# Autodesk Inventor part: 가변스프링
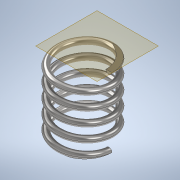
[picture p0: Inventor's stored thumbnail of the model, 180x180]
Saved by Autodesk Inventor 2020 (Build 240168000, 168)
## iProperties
Created: 2022-09
Part Number: 가변스프링
Material: 스테인레스 스틸
Document SubType Name: Modeling
Designer: 101-13
Mass: 6.62074 g
Surface Area: 16.7829 cm^2
Volume: 0.827592 cm^3
Density: 8 g/cm^3
Appearance: 반연마
Author: 101-13
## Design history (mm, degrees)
node "작업 평면1"
sketch "스케치1"
  geometry: L1 (-1.9, 22.5)-(11.4, 22.5) reference; L2 (0, 0)-(8.5, 0); L3 (8.5, 0)-(8.5, 21.871); L4 (8.5, 21.871)-(0, 21.871); L5 (0, 21.871)-(0, 0); C1 r 1 at (8.5, 0)
  constraints: 8 end point, 2 parallel, 1 centre point, 1 coincident, 1 horizontal, 1 perpendicular
  dimensions: "d1" = 22.5 distance from line of L1 L2.start (derived); "d2" = 2 diameter of C1; "d3" = 17 diameter of L3 L5
feature "코일1" sketch "스케치1" pitch "d4" = 10; turns "d6" = 5; dims "d5" = 22.5 (= HEIGHT), "d7" = 0, angle "d8" = 90 deg, angle "d9" = 90 deg, "d10" = 0, "d11" = 0
feature "분할1"
feature "분할2"
node "솔리드1"
other parameters: "HEIGHT" = 22.5 (= d1) [user parameter; used in 1 equation term]
